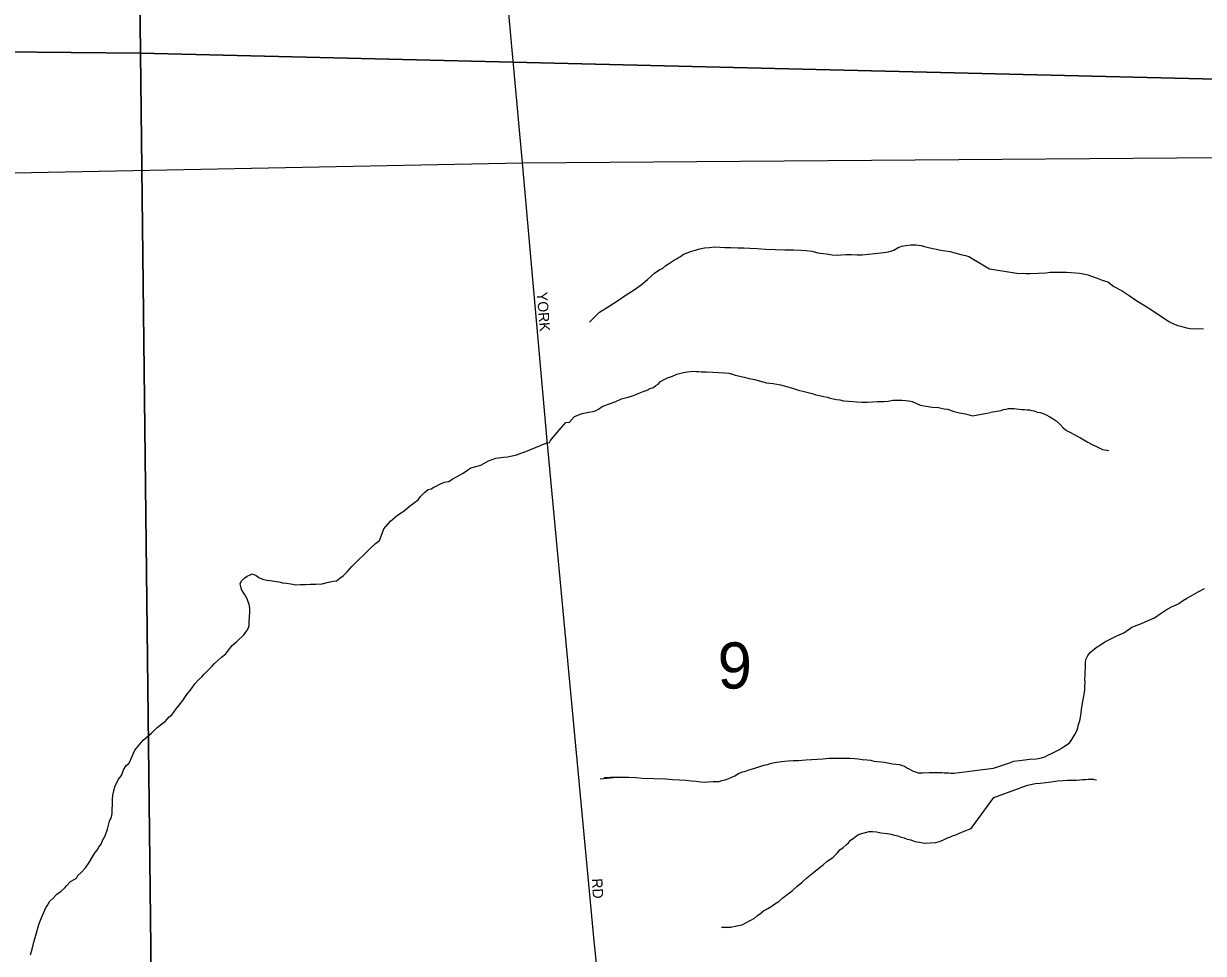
# Model space of a CAD drawing. Extents: x 2010165 to 2382125, y 1060529 to 1407316.
# Drawn here: x 2169958 to 2175609, y 1212363 to 1216816 of the extents above; entities that cross this region are included whole.
import ezdxf

# ---------------------------------------------------------------- set-up
doc = ezdxf.new("R2010")
doc.units = 0
for name, color, linetype in [('GM_X_City_Street', 7, 'Continuous'), ('GM_X_City_Street_Text', 7, 'Continuous'), ('GM_X_Minor_River', 7, 'Continuous'), ('GM_X_Section', 7, 'Continuous'), ('GM_X_Section_Text', 7, 'Continuous')]:
    doc.layers.add(name, color=color, linetype=linetype)

msp = doc.modelspace()

# ---------------------------------------------------------------- linework, layer by layer
at = {"layer": 'GM_X_City_Street'}
for points in [[(2172692.8, 1212405.1), (2172464.7, 1214818.9), (2172347.5, 1216149.6), (2171993.3, 1220019.4), (2171878.7, 1221123.6), (2171877.5, 1221144)], [(2172347.5, 1216149.6), (2178406.5, 1216195.6)], [(2164844.7, 1216037.6), (2167420.4, 1216057.6), (2168738.1, 1216077.8), (2169831.9, 1216100.1), (2172347.5, 1216149.6)], [(2172972.5, 1209345.9), (2172864, 1210529.5), (2172719.8, 1212136.6), (2172693.8, 1212394.4), (2172692.8, 1212405.1)]]:
    msp.add_lwpolyline(points, dxfattribs=at)
at = {"layer": 'GM_X_Minor_River'}
for points in [[(2172668, 1215386), (2172715.4, 1215434.7), (2172763.1, 1215463.4), (2172806.8, 1215492), (2172844.6, 1215516.6), (2172882.3, 1215541.1), (2172916.1, 1215565.6), (2172945.8, 1215590), (2172979.5, 1215620.6), (2173005.3, 1215638.9), (2173017.2, 1215643.1), (2173033.1, 1215657.3), (2173047, 1215665.5), (2173056.9, 1215671.6), (2173070.8, 1215681.9), (2173084.7, 1215690.1), (2173094.7, 1215696.2), (2173104.6, 1215700.3), (2173118.5, 1215712.5), (2173132.5, 1215716.7), (2173152.4, 1215725), (2173176.4, 1215731.3), (2173196.3, 1215737.6), (2173218.3, 1215741.8), (2173242.3, 1215744.1), (2173266.3, 1215746.4), (2173292.4, 1215744.8), (2173316.4, 1215743.1), (2173344.5, 1215743.4), (2173378.6, 1215741.8), (2173406.6, 1215742.1), (2173436.7, 1215740.5), (2173470.8, 1215738.9), (2173510.9, 1215735.4), (2173557, 1215734), (2173603.1, 1215732.5), (2173647.2, 1215733.1), (2173681.2, 1215731.5), (2173705.3, 1215729.8), (2173733.4, 1215726.1), (2173761.5, 1215718.4), (2173801.7, 1215712.9), (2173829.8, 1215709.2), (2173855.9, 1215707.5), (2173875.9, 1215707.8), (2173895.9, 1215710), (2173921.9, 1215710.3), (2173950, 1215708.7), (2173974, 1215709), (2174034.1, 1215715.7), (2174078.1, 1215720.3), (2174100.1, 1215722.5), (2174112.1, 1215726.7), (2174126, 1215730.9), (2174145.9, 1215743.2), (2174163.8, 1215749.4), (2174183.8, 1215753.7), (2174207.8, 1215756), (2174231.9, 1215756.2), (2174256, 1215752.5), (2174272, 1215748.7), (2174292.2, 1215742.9), (2174312.2, 1215739.2), (2174330.3, 1215735.4), (2174350.4, 1215731.6), (2174372.5, 1215727.9), (2174394.6, 1215724.1), (2174418.7, 1215718.4), (2174446.8, 1215710.7), (2174469, 1215705), (2174485, 1215701.2), (2174583.3, 1215642)], [(2174583.3, 1215641.5), (2174724.1, 1215619.7), (2174740.1, 1215620.1), (2174758.2, 1215618.6), (2174780.3, 1215619.2), (2174854.4, 1215623.1), (2174874.4, 1215625.6), (2174898.4, 1215626.3), (2174930.5, 1215625.1), (2174952.6, 1215625.7), (2174974.6, 1215624.3), (2174996.7, 1215622.8), (2175014.8, 1215621.3), (2175035, 1215617.8), (2175055.2, 1215612.3), (2175077.4, 1215604.9), (2175099.7, 1215597.4), (2175124, 1215588), (2175150.3, 1215578.7), (2175179, 1215557.4), (2175219.7, 1215536.3), (2175252.4, 1215513.1), (2175289.1, 1215488), (2175329.9, 1215464.9), (2175364.6, 1215441.8), (2175395.2, 1215420.5), (2175421.8, 1215403.1), (2175442.2, 1215389.6), (2175464.6, 1215378.1), (2175486.8, 1215370.7), (2175505, 1215365.1), (2175527.2, 1215359.7), (2175545.4, 1215356.2), (2175565.5, 1215354.7), (2175585.5, 1215355.2), (2175609.6, 1215353.8)], [(2171157.5, 1214145.6), (2171179.6, 1214141.9), (2171197.7, 1214138.1), (2171217.7, 1214136.4), (2171237.8, 1214132.6), (2171261.9, 1214128.9), (2171284, 1214129.1), (2171308, 1214129.4), (2171332, 1214131.7), (2171356, 1214132), (2171388.1, 1214132.4), (2171418, 1214140.8), (2171440, 1214145.1), (2171456, 1214147.3), (2171471.9, 1214159.5), (2171487.8, 1214171.8), (2171507.6, 1214190.1), (2171529.2, 1214216.4), (2171558.9, 1214244.9), (2171588.6, 1214273.3), (2171618.3, 1214301.8), (2171644, 1214326.2), (2171661.9, 1214340.4), (2171669.6, 1214360.6), (2171683.2, 1214396.9), (2171714.7, 1214433.4), (2171748.4, 1214461.9), (2171780.2, 1214482.3), (2171804, 1214502.7), (2171829.8, 1214523), (2171847.6, 1214535.3), (2171859.5, 1214551.5), (2171877.2, 1214569.8), (2171895.1, 1214584), (2171909.1, 1214588.2), (2171923, 1214596.4), (2171936.9, 1214602.6), (2171948.9, 1214608.8), (2171972.8, 1214619.1), (2171994.7, 1214623.4), (2172010.6, 1214633.6), (2172030.5, 1214645.9), (2172062.4, 1214662.3), (2172100.1, 1214688.9), (2172148, 1214701.5), (2172161.9, 1214709.7), (2172183.8, 1214722), (2172219.7, 1214734.5), (2172255.7, 1214738.9), (2172275.7, 1214741.2), (2172297.7, 1214745.4), (2172313.7, 1214749.7), (2172327.6, 1214753.8), (2172339.6, 1214758), (2172355.5, 1214764.2), (2172463.2, 1214807.7), (2172477.2, 1214809.8), (2172481, 1214819.9), (2172494.8, 1214836.1), (2172512.6, 1214858.4), (2172532.3, 1214880.8), (2172554.1, 1214905.1), (2172572.1, 1214907.3), (2172595.7, 1214933.7), (2172633.6, 1214948.2), (2172665.6, 1214954.6), (2172685.6, 1214958.9), (2172699.5, 1214963), (2172711.5, 1214969.2), (2172729.4, 1214981.5), (2172771.2, 1214998), (2172795.1, 1215006.3), (2172821, 1215018.7), (2172853, 1215027.1), (2172878.9, 1215035.5), (2172900.8, 1215043.8), (2172924.8, 1215054.1), (2172944.7, 1215060.3), (2172958.6, 1215068.5), (2172974.6, 1215072.8), (2172986.5, 1215082.9), (2172996.4, 1215089.1), (2173008.3, 1215101.2), (2173026.2, 1215111.5), (2173042.1, 1215119.7), (2173056.1, 1215123.9), (2173066, 1215128), (2173086, 1215136.3), (2173099.9, 1215140.5), (2173117.9, 1215144.7), (2173137.9, 1215149), (2173165.9, 1215151.3), (2173180, 1215149.5), (2173190, 1215149.6), (2173204, 1215147.8), (2173228.1, 1215148.1), (2173314.3, 1215143.1), (2173336.3, 1215141.4), (2173352.4, 1215137.6), (2173366.5, 1215131.7), (2173388.6, 1215128)], [(2173388.6, 1215128), (2173408.7, 1215122.2), (2173432.8, 1215116.5), (2173458.9, 1215110.8), (2173487.1, 1215103.1), (2173515.2, 1215095.4), (2173547.3, 1215091.8), (2173583.5, 1215086.2), (2173617.7, 1215076.6), (2173645.8, 1215068.9), (2173670, 1215061.2), (2173696.1, 1215053.5), (2173716.2, 1215049.7), (2173734.3, 1215043.9), (2173752.4, 1215038.1), (2173770.5, 1215034.3), (2173790.6, 1215030.6), (2173808.6, 1215026.8), (2173820.7, 1215022.9), (2173834.8, 1215019.1), (2173850.9, 1215015.2), (2173866.9, 1215013.4), (2173885, 1215009.6), (2173909.1, 1215007.9), (2173929.1, 1215006.2), (2173949.2, 1215004.4), (2173973.2, 1215002.7), (2173997.3, 1215003), (2174025.3, 1215005.3), (2174047.3, 1215005.6), (2174059.4, 1215005.8), (2174069.4, 1215005.9), (2174079.4, 1215006), (2174099.4, 1215008.2), (2174121.4, 1215012.5), (2174147.4, 1215012.9), (2174165.4, 1215013.1), (2174183.5, 1215011.3), (2174197.5, 1215009.4), (2174213.6, 1215005.6), (2174231.8, 1214997.8), (2174251.9, 1214988.1), (2174310.2, 1214978.7), (2174340.2, 1214977.1), (2174366.3, 1214971.4), (2174382.4, 1214969.6), (2174414.6, 1214957.9), (2174440.7, 1214952.2), (2174468.8, 1214946.6), (2174491, 1214940.8), (2174503, 1214936.9), (2174589, 1214953.8)], [(2174588.9, 1214955.6), (2174639.6, 1214962.9), (2174651.5, 1214967.2), (2174663.5, 1214969.6), (2174675.4, 1214971.9), (2174687.4, 1214972.2), (2174701.5, 1214972.6), (2174711.5, 1214970.8), (2174725.6, 1214969.2), (2174739.7, 1214967.5), (2174751.7, 1214967.9), (2174763.8, 1214966.2), (2174775.8, 1214966.5), (2174786, 1214962.7), (2174798, 1214961.1), (2174812.2, 1214955.4), (2174826.3, 1214953.8), (2174838.4, 1214950.1), (2174854.7, 1214942.5), (2174873, 1214932.9), (2174889.3, 1214923.3), (2174903.6, 1214913.6), (2174922.1, 1214896), (2174936.6, 1214880.4), (2174953, 1214866.7), (2174971.3, 1214857.2), (2174989.6, 1214847.6), (2175003.8, 1214840), (2175020.1, 1214832.4), (2175036.4, 1214822.8), (2175054.7, 1214811.2), (2175075.1, 1214799.7), (2175099.5, 1214788.3), (2175125.9, 1214776.9), (2175156.1, 1214771.7)], [(2169998.5, 1212384), (2170006.1, 1212416.2), (2170033, 1212506.8), (2170042.7, 1212531), (2170052.4, 1212555.2), (2170062.1, 1212577.4), (2170069.9, 1212591.5), (2170083.7, 1212613.8), (2170099.5, 1212628), (2170117.3, 1212646.3), (2170137.1, 1212660.6), (2170153, 1212674.8), (2170164.8, 1212689), (2170182.6, 1212707.3), (2170200.5, 1212717.5), (2170210.4, 1212723.7), (2170218.3, 1212735.8), (2170234.1, 1212750), (2170253.9, 1212772.3), (2170271.6, 1212798.6), (2170287.2, 1212824.9), (2170301, 1212847.1), (2170310.9, 1212857.3), (2170318.7, 1212871.4), (2170328.5, 1212885.6), (2170336.3, 1212903.8), (2170348, 1212926), (2170359.6, 1212958.2), (2170369.2, 1212996.4), (2170378.9, 1213016.6), (2170382.7, 1213032.7), (2170382.4, 1213052.8), (2170384.1, 1213076.9), (2170383.8, 1213100.9), (2170385.6, 1213121), (2170395, 1213161.3), (2170412.6, 1213197.6), (2170426.4, 1213215.8), (2170438, 1213246.1), (2170449.8, 1213262.3), (2170461.7, 1213272.4), (2170467.6, 1213284.5), (2170473.4, 1213296.6), (2170490.9, 1213337), (2170530.4, 1213383.6), (2170570, 1213418.2), (2170597.7, 1213444.6), (2170619.5, 1213462.9), (2170635.4, 1213473.2), (2170645.3, 1213485.3), (2170655.1, 1213495.5), (2170667, 1213505.7), (2170676.9, 1213517.8), (2170688.7, 1213534), (2170702.5, 1213552.2), (2170720.2, 1213574.5), (2170739.9, 1213602.8), (2170759.6, 1213629.2), (2170777.3, 1213653.5), (2170795.1, 1213673.8), (2170810.9, 1213688), (2170820.8, 1213698.1), (2170830.7, 1213708.3), (2170840.5, 1213718.4), (2170860.3, 1213738.8), (2170872.2, 1213750.9), (2170888, 1213765.2), (2170905.8, 1213781.4), (2170925.7, 1213797.7), (2170939.4, 1213816), (2170957.2, 1213838.2), (2170979, 1213856.6), (2171012.6, 1213889.1), (2171020.5, 1213899.2), (2171030.3, 1213913.4), (2171034.2, 1213923.4), (2171038.1, 1213933.5), (2171037.8, 1213951.6), (2171039.5, 1213975.7), (2171041.3, 1213995.8), (2171041, 1214015.8), (2171038.8, 1214033.9), (2171032.5, 1214051.8), (2171028.4, 1214061.8), (2171022.3, 1214071.8), (2171016.1, 1214083.7), (2171009.9, 1214093.7), (2171001.8, 1214105.6), (2170997.6, 1214119.6), (2170995.4, 1214133.6), (2171001.2, 1214147.8), (2171017.1, 1214162), (2171029, 1214170.2), (2171042.9, 1214176.4), (2171052.9, 1214180.5), (2171071, 1214172.7), (2171085.2, 1214162.8), (2171101.3, 1214155), (2171123.4, 1214151.3), (2171139.4, 1214149.4), (2171157.5, 1214145.6)], [(2174603.1, 1213250.5), (2174685.1, 1213277.5), (2174700.9, 1213284), (2174726.9, 1213286.7), (2174752.9, 1213289.4), (2174774.9, 1213294), (2174808.9, 1213294.8), (2174832.9, 1213299.5), (2174848.8, 1213303.9), (2174862.6, 1213312.3), (2174880.4, 1213320.8), (2174900.2, 1213329.4), (2174920, 1213339.9), (2174937.7, 1213352.4), (2174955.5, 1213363), (2174969.2, 1213373.4), (2174978.9, 1213387.7), (2174992.3, 1213412.1), (2175001.8, 1213428.4), (2175007.5, 1213442.6), (2175011, 1213458.8), (2175016.6, 1213477), (2175020.1, 1213495.2), (2175023.6, 1213513.3), (2175025.1, 1213531.4), (2175028.6, 1213551.6), (2175039, 1213612.1), (2175040.6, 1213626.2), (2175040.2, 1213642.3), (2175041.7, 1213660.4), (2175041.2, 1213678.4), (2175042.8, 1213694.5), (2175042.3, 1213712.6), (2175043.9, 1213728.7), (2175043.5, 1213742.7), (2175043.2, 1213754.8), (2175044.7, 1213770.9), (2175054.3, 1213789.2), (2175065.9, 1213803.6), (2175077.7, 1213813.9), (2175095.3, 1213828.4), (2175115, 1213841), (2175136.7, 1213855.6), (2175162.4, 1213868.3), (2175194.1, 1213883.2), (2175227.8, 1213898.2), (2175265.2, 1213925.2), (2175312.8, 1213942.6), (2175344.5, 1213957.4), (2175374.2, 1213970.3), (2175401.8, 1213989.1), (2175429.4, 1214007.9), (2175455, 1214022.6), (2175474.9, 1214031.1), (2175490.7, 1214039.6), (2175508.4, 1214052.1), (2175528.2, 1214062.7), (2175549.9, 1214075.3), (2175583.5, 1214094.2), (2175613.1, 1214111.1)], [(2172718.6, 1213199.7), (2172798.6, 1213206.7), (2172738.6, 1213204), (2172798.6, 1213206.7), (2172824.7, 1213207), (2172856.7, 1213207.4), (2172890.8, 1213205.8), (2172920.9, 1213202.2), (2173033.1, 1213199.5), (2173065.2, 1213195.9), (2173099.3, 1213194.3), (2173129.4, 1213192.7), (2173157.5, 1213189), (2173179.5, 1213187.3), (2173199.6, 1213185.5), (2173219.7, 1213183.8), (2173237.7, 1213184), (2173259.7, 1213186.3), (2173275.7, 1213186.4), (2173289.7, 1213186.6), (2173301.7, 1213190.8), (2173317.7, 1213195), (2173335.6, 1213201.2), (2173349.6, 1213207.4), (2173363.5, 1213213.6), (2173381.4, 1213223.9), (2173401.3, 1213232.1), (2173417.3, 1213236.3), (2173431.3, 1213242.5), (2173455.2, 1213248.8), (2173475.2, 1213255.1), (2173493.1, 1213261.3), (2173511.1, 1213265.6), (2173523.1, 1213267.7), (2173533.1, 1213271.9), (2173555, 1213278.1), (2173587, 1213282.6), (2173619, 1213284.9), (2173643, 1213287.2), (2173669.1, 1213287.6), (2173705.1, 1213290), (2173731.1, 1213292.3), (2173759.2, 1213292.7), (2173785.2, 1213295), (2173815.2, 1213297.4), (2173843.3, 1213297.7), (2173871.3, 1213298.1), (2173895.3, 1213298.4), (2173917.4, 1213298.6), (2173939.4, 1213296.9), (2173955.5, 1213295.1), (2173973.6, 1213291.3), (2173997.6, 1213289.6), (2174013.7, 1213287.8), (2174029.8, 1213283.9), (2174045.8, 1213282.1), (2174065.9, 1213280.4), (2174079.9, 1213278.6), (2174120.1, 1213271), (2174136.1, 1213269.2), (2174152.2, 1213267.4), (2174166.3, 1213263.6), (2174176.3, 1213259.7), (2174190.5, 1213249.8), (2174200.6, 1213245.9), (2174218.7, 1213236.1), (2174228.8, 1213232.2), (2174242.9, 1213228.4), (2174264.9, 1213228.6), (2174294.9, 1213229), (2174311, 1213229.2), (2174325, 1213229.4), (2174339, 1213229.6), (2174357, 1213229.8), (2174367.1, 1213227.9), (2174377.1, 1213228), (2174389.1, 1213228.2), (2174399.2, 1213226.3), (2174413.2, 1213226.4), (2174603.1, 1213250.4)], [(2174604.3, 1213110.1), (2174722.5, 1213152.1), (2174744.4, 1213160.6), (2174768.2, 1213169.3), (2174802.1, 1213176.2), (2174826.1, 1213178.9), (2174854.1, 1213181.6), (2174880.1, 1213184.3), (2174910, 1213189.1), (2174936, 1213191.8), (2174958.1, 1213192.4), (2174980.1, 1213192.9), (2175000.2, 1213193.5), (2175016.2, 1213193.9), (2175030.2, 1213196.3), (2175044.2, 1213196.6), (2175056.2, 1213197), (2175066.2, 1213197.2), (2175084.3, 1213195.7), (2175066.2, 1213197.2), (2175084.3, 1213195.7), (2175096.4, 1213194)], [(2173300.9, 1212486.6), (2173345, 1212489.1), (2173300.9, 1212486.6), (2173345, 1212489.1), (2173372.9, 1212495.5), (2173398.9, 1212499.8), (2173416.8, 1212510.1), (2173440.7, 1212522.4), (2173458.6, 1212532.6), (2173472.4, 1212544.8), (2173488.3, 1212555.1), (2173502.2, 1212567.3), (2173522.1, 1212577.6), (2173538, 1212587.8), (2173555.9, 1212600), (2173575.7, 1212612.3), (2173593.6, 1212628.6), (2173615.4, 1212644.9), (2173639.2, 1212663.2), (2173661, 1212683.6), (2173686.7, 1212703.9), (2173708.5, 1212724.3), (2173732.3, 1212744.6), (2173766, 1212771.1), (2173787.8, 1212787.4), (2173805.6, 1212803.7), (2173821.5, 1212813.9), (2173833.5, 1212822.1), (2173843.3, 1212832.3), (2173855.2, 1212844.4), (2173867, 1212858.6), (2173882.9, 1212870.9), (2173896.8, 1212883.1), (2173908.7, 1212893.2), (2173918.5, 1212905.4), (2173930.4, 1212913.6), (2173946.3, 1212925.8), (2173956.2, 1212932), (2173966.2, 1212936.1), (2174008.1, 1212946.6), (2174024.2, 1212946.8), (2174042.2, 1212945.1), (2174064.3, 1212941.3), (2174094.4, 1212937.7), (2174112.5, 1212933.9), (2174128.6, 1212930.1), (2174144.6, 1212926.2), (2174160.7, 1212920.4), (2174174.8, 1212916.6), (2174188.9, 1212910.7), (2174207, 1212906.9), (2174227.1, 1212899.2), (2174249.2, 1212895.4), (2174273.3, 1212891.7), (2174299.3, 1212892), (2174327.4, 1212894.4), (2174345.3, 1212898.6), (2174363.3, 1212906.8), (2174383.2, 1212917.1), (2174397.1, 1212921.3), (2174407.1, 1212925.4), (2174423, 1212931.6), (2174433, 1212935.8), (2174450.9, 1212944), (2174466.9, 1212950.2), (2174482.8, 1212956.4), (2174496.8, 1212960.6), (2174604.3, 1213109.8)], [(2169990.9, 1212355.8), (2169998.5, 1212384)]]:
    msp.add_lwpolyline(points, dxfattribs=at)
at = {"layer": 'GM_X_Section'}
for points in [[(2175291.6, 1221576.6), (2176081.6, 1221585.6), (2176133.3, 1216538.6), (2170517.3, 1216673.9), (2170463.9, 1221481), (2171925.4, 1221504.9), (2174244.4, 1221580)], [(2168586.2, 1221473.3), (2170463.9, 1221481), (2170517.3, 1216673.9), (2164881.3, 1216727.8), (2164874, 1218333.8), (2164860.8, 1221446.2)], [(2170517.3, 1216673.9), (2170583.9, 1211012.5), (2164931.4, 1211072.2), (2164907.3, 1213281.5), (2164886.2, 1215783.6), (2164881.3, 1216727.8)], [(2176133.3, 1216538.6), (2176227.8, 1210985.9), (2170583.9, 1211012.5), (2170517.3, 1216673.9)]]:
    msp.add_lwpolyline(points, close=True, dxfattribs=at)

# ---------------------------------------------------------------- texts
at = {"layer": 'GM_X_City_Street_Text'}
for s, rotation, p in [('YORK', 274.3961, (2172415.6, 1215528.3)), ('RD', 273.011, (2172679.6, 1212720.9))]:
    msp.add_text(s, height=50, rotation=rotation, dxfattribs=at).set_placement(p)
at = {"layer": 'GM_X_Section_Text'}
msp.add_text('9', height=221, rotation=0, dxfattribs=at).set_placement((2173281.8, 1213631.5))

doc.saveas('drawing.dxf')
